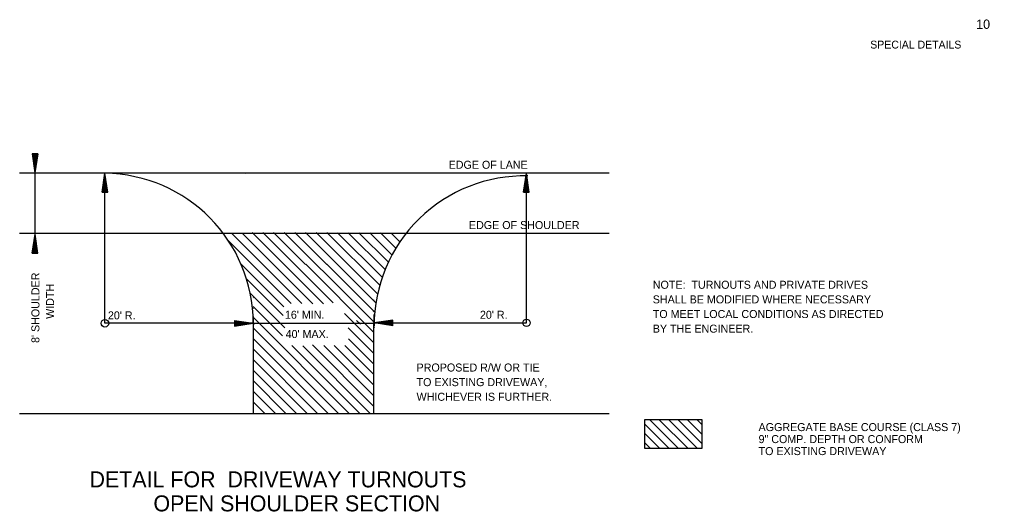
# Model space of a CAD drawing. Extents: x 635488 to 635865, y 290537 to 290973.
# Drawn here: x 635707.6 to 635780.4, y 290932.7 to 290969.7 of the extents above; entities that cross this region are included whole.
import ezdxf

# ---------------------------------------------------------------- set-up
doc = ezdxf.new("R2010")
doc.units = 0
for name, color, linetype in [('Default', 7, 'Continuous'), ('E_Existing ROW', 7, 'Continuous'), ('R_Alt Surface', 7, 'Continuous'), ('R_Alt Surface Annot', 7, 'Continuous')]:
    doc.layers.add(name, color=color, linetype=linetype)

msp = doc.modelspace()

# ---------------------------------------------------------------- linework, layer by layer
at = {"layer": 'Default'}
for p, q in [((635708.577, 290959.558), (635708.789, 290958.143)), ((635709.002, 290959.558), (635708.577, 290959.558)), ((635708.61, 290959.558), (635708.789, 290958.378)), ((635708.65, 290959.558), (635708.789, 290958.621)), ((635708.686, 290959.558), (635708.789, 290958.857)), ((635708.72, 290959.558), (635708.789, 290959.098)), ((635708.756, 290959.558), (635708.789, 290959.329)), ((635709.002, 290959.558), (635708.789, 290958.143)), ((635708.855, 290959.558), (635708.789, 290959.098)), ((635708.932, 290959.558), (635708.789, 290958.621)), ((635708.968, 290959.558), (635708.789, 290958.378)), ((635708.893, 290959.558), (635708.789, 290958.857)), ((635708.823, 290959.558), (635708.789, 290959.329)), ((635707.625, 290958.143), (635751.829, 290958.143)), ((635708.795, 290953.624), (635708.795, 290958.143)), ((635713.824, 290956.695), (635714.036, 290958.107)), ((635713.857, 290956.695), (635714.036, 290957.869)), ((635714.246, 290956.695), (635714.036, 290958.107)), ((635714.036, 290946.854), (635714.036, 290958.107)), ((635714.212, 290956.695), (635714.036, 290957.869)), ((635724.547, 290958.096), (635724.567, 290958.157)), ((635724.567, 290958.137), (635724.547, 290958.096)), ((635724.547, 290958.096), (635724.567, 290958.116)), ((635745.428, 290956.701), (635745.641, 290958.116)), ((635745.462, 290956.701), (635745.641, 290957.874)), ((635745.853, 290956.701), (635745.641, 290958.116)), ((635745.641, 290946.884), (635745.641, 290958.116)), ((635745.816, 290956.701), (635745.641, 290957.874)), ((635713.893, 290956.695), (635714.036, 290957.626)), ((635713.929, 290956.695), (635714.036, 290957.393)), ((635713.969, 290956.695), (635714.036, 290957.152)), ((635714.176, 290956.695), (635714.036, 290957.626)), ((635714.139, 290956.695), (635714.036, 290957.393)), ((635714.105, 290956.695), (635714.036, 290957.152)), ((635745.498, 290956.701), (635745.641, 290957.633)), ((635745.534, 290956.701), (635745.641, 290957.399)), ((635745.569, 290956.701), (635745.641, 290957.158)), ((635745.78, 290956.701), (635745.641, 290957.633)), ((635745.744, 290956.701), (635745.641, 290957.399)), ((635745.71, 290956.701), (635745.641, 290957.158)), ((635713.824, 290956.695), (635714.246, 290956.695)), ((635714.001, 290956.695), (635714.036, 290956.917)), ((635714.07, 290956.695), (635714.036, 290956.917)), ((635745.428, 290956.701), (635745.853, 290956.701)), ((635745.605, 290956.701), (635745.641, 290956.923)), ((635745.674, 290956.701), (635745.641, 290956.923)), ((635707.625, 290953.624), (635751.829, 290953.624)), ((635708.587, 290952.12), (635708.798, 290953.535)), ((635709.011, 290952.12), (635708.798, 290953.535)), ((635708.622, 290952.12), (635708.798, 290953.293)), ((635708.658, 290952.12), (635708.798, 290953.053)), ((635708.691, 290952.12), (635708.798, 290952.818)), ((635708.974, 290952.12), (635708.798, 290953.293)), ((635708.941, 290952.12), (635708.798, 290953.053)), ((635708.9, 290952.12), (635708.798, 290952.818)), ((635708.587, 290952.12), (635709.011, 290952.12)), ((635708.73, 290952.12), (635708.798, 290952.577)), ((635708.765, 290952.12), (635708.798, 290952.343)), ((635708.867, 290952.12), (635708.798, 290952.577)), ((635708.831, 290952.12), (635708.798, 290952.343)), ((635729.092, 290951.29), (635734.196, 290946.17)), ((635730.681, 290951.281), (635734.262, 290947.69)), ((635724.649, 290950.198), (635727.409, 290947.428)), ((635732.881, 290949.867), (635734.35, 290948.394)), ((635724.928, 290949.125), (635727.532, 290946.514)), ((635725.923, 290949.622), (635727.445, 290948.096)), ((635725.158, 290948.102), (635727.35, 290945.903)), ((635733.116, 290948.046), (635734.196, 290946.962)), ((635723.746, 290947.064), (635725.158, 290946.854)), ((635723.746, 290947.064), (635723.746, 290946.64)), ((635723.746, 290947.031), (635724.919, 290946.854)), ((635723.746, 290946.994), (635724.679, 290946.854)), ((635723.746, 290946.953), (635724.442, 290946.854)), ((635723.746, 290946.922), (635724.203, 290946.854)), ((635725.158, 290947.352), (635725.158, 290946.824)), ((635725.158, 290947.31), (635732.352, 290940.094)), ((635731.993, 290947.586), (635734.196, 290945.377)), ((635734.196, 290947.505), (635734.196, 290946.86)), ((635735.626, 290947.097), (635734.215, 290946.884)), ((635735.626, 290947.064), (635734.451, 290946.884)), ((635735.626, 290947.028), (635734.694, 290946.884)), ((635735.626, 290946.991), (635734.927, 290946.884)), ((635735.626, 290946.958), (635735.167, 290946.884)), ((635735.626, 290946.918), (635735.402, 290946.884)), ((635735.626, 290946.675), (635735.626, 290947.097)), ((635725.158, 290946.854), (635714.036, 290946.854)), ((635723.746, 290946.886), (635723.967, 290946.854)), ((635723.746, 290946.64), (635725.158, 290946.854)), ((635723.746, 290946.782), (635724.203, 290946.854)), ((635723.746, 290946.711), (635724.679, 290946.854)), ((635723.746, 290946.673), (635724.919, 290946.854)), ((635723.746, 290946.747), (635724.442, 290946.854)), ((635723.746, 290946.819), (635723.967, 290946.854)), ((635725.158, 290946.854), (635725.158, 290940.094)), ((635725.158, 290946.854), (635733.126, 290946.854)), ((635725.158, 290946.518), (635731.56, 290940.094)), ((635732.268, 290946.518), (635734.196, 290944.585)), ((635732.904, 290946.854), (635734.247, 290946.854)), ((635734.196, 290940.082), (635734.196, 290946.884)), ((635735.626, 290946.675), (635734.215, 290946.884)), ((635734.215, 290946.884), (635745.641, 290946.884)), ((635735.626, 290946.709), (635734.451, 290946.884)), ((635735.626, 290946.744), (635734.694, 290946.884)), ((635735.626, 290946.782), (635734.927, 290946.884)), ((635735.626, 290946.818), (635735.167, 290946.884)), ((635735.626, 290946.851), (635735.402, 290946.884)), ((635725.158, 290945.724), (635730.77, 290940.094)), ((635732.299, 290945.696), (635734.196, 290943.792)), ((635725.158, 290944.932), (635729.98, 290940.094)), ((635728.051, 290945.198), (635733.14, 290940.094)), ((635728.874, 290945.167), (635733.932, 290940.094)), ((635729.59, 290945.243), (635734.196, 290940.622)), ((635730.441, 290945.179), (635734.196, 290941.413)), ((635731.233, 290945.177), (635734.196, 290942.207)), ((635732.026, 290945.176), (635734.196, 290943)), ((635725.158, 290944.138), (635729.188, 290940.094)), ((635725.158, 290943.344), (635728.4, 290940.094)), ((635725.158, 290942.552), (635727.61, 290940.094)), ((635725.158, 290941.76), (635726.818, 290940.094)), ((635725.158, 290940.968), (635726.03, 290940.094)), ((635707.625, 290940.094), (635751.829, 290940.094))]:
    msp.add_line(p, q, dxfattribs=at)
for points in [[(635723.526, 290953.624), (635728.808, 290948.338)], [(635724.323, 290953.624), (635729.63, 290948.322)], [(635725.069, 290953.677), (635730.432, 290948.315)], [(635725.868, 290953.674), (635731.16, 290948.386)], [(635726.671, 290953.671), (635729.071, 290951.27)], [(635727.471, 290953.665), (635733.11, 290948.04)], [(635728.271, 290953.665), (635730.669, 290951.27)], [(635729.08, 290953.663), (635732.881, 290949.867)], [(635729.877, 290953.66), (635732.274, 290951.27)], [(635730.678, 290953.657), (635734.636, 290949.702)], [(635731.481, 290953.651), (635734.827, 290950.308)], [(635732.28, 290953.651), (635735.047, 290950.895)], [(635733.083, 290953.651), (635735.289, 290951.449)], [(635733.886, 290953.648), (635735.557, 290951.977)], [(635734.688, 290953.648), (635735.848, 290952.487)], [(635735.504, 290953.624), (635736.158, 290952.97)], [(635723.286, 290953.065), (635728.004, 290948.343)], [(635724.233, 290951.319), (635725.923, 290949.622)], [(635732.272, 290951.27), (635734.475, 290949.059)], [(635725.158, 290948.797), (635725.18, 290948.774)], [(635734.135, 290948.609), (635734.196, 290948.547)], [(635725.158, 290947.998), (635725.174, 290947.974)], [(635734.137, 290947.8), (635734.229, 290947.71)], [(635725.152, 290947.204), (635725.171, 290947.182)], [(635732.904, 290947.075), (635733.194, 290946.78)], [(635734.139, 290947), (635734.196, 290946.946)], [(635725.171, 290946.816), (635725.228, 290946.758)], [(635734.175, 290946.598), (635734.242, 290946.534)]]:
    msp.add_lwpolyline(points, dxfattribs=at)
for centre in [(635714.036, 290946.854), (635745.64, 290946.885)]:
    msp.add_circle(centre, 0.282, dxfattribs=at)
for centre, radius, start, end in [((635713.893, 290946.839), 11.268, 0.07639, 89.27429), ((635745.485, 290946.64), 11.273, 88.75379, 180)]:
    msp.add_arc(centre, radius, start, end, dxfattribs=at)
at = {"layer": 'E_Existing ROW'}
for p, q in [((635757.05, 290937.452), (635754.868, 290939.635)), ((635757.757, 290937.452), (635755.575, 290939.635)), ((635758.464, 290937.452), (635756.282, 290939.635)), ((635758.789, 290937.835), (635756.989, 290939.635)), ((635758.789, 290938.542), (635757.696, 290939.635)), ((635758.789, 290939.249), (635758.403, 290939.635)), ((635756.343, 290937.452), (635754.508, 290939.287)), ((635755.636, 290937.452), (635754.508, 290938.58)), ((635754.928, 290937.452), (635754.508, 290937.873))]:
    msp.add_line(p, q, dxfattribs=at)
msp.add_lwpolyline([(635754.508, 290939.635), (635758.789, 290939.635), (635758.789, 290937.452), (635754.508, 290937.452)], close=True, dxfattribs=at)

# ---------------------------------------------------------------- texts
at = {"layer": 'Default'}
for s, height, p in [('EDGE OF LANE', 0.6, (635739.805, 290958.447)), ('EDGE OF SHOULDER', 0.6, (635741.327, 290953.923)), ('NOTE:  TURNOUTS AND PRIVATE DRIVES', 0.6, (635755.111, 290949.444)), ('SHALL BE MODIFIED WHERE NECESSARY', 0.6, (635755.111, 290948.346)), ("20' R.", 0.6, (635714.261, 290947.148)), ("16' MIN.", 0.6, (635727.53, 290947.195)), ("20' R.", 0.6, (635742.153, 290947.194)), ('TO MEET LOCAL CONDITIONS AS DIRECTED', 0.6, (635755.111, 290947.249)), ("40' MAX.", 0.6, (635727.584, 290945.747)), ('BY THE ENGINEER.', 0.6, (635755.111, 290946.151)), ('PROPOSED R/W OR TIE', 0.6, (635737.401, 290943.236)), ('TO EXISTING DRIVEWAY,', 0.6, (635737.401, 290942.138)), ('WHICHEVER IS FURTHER.', 0.6, (635737.401, 290941.041)), ('DETAIL FOR  DRIVEWAY TURNOUTS', 1.2, (635712.881, 290934.544)), ('OPEN SHOULDER SECTION', 1.2, (635717.673, 290932.742))]:
    msp.add_text(s, height=height, dxfattribs=at).set_placement(p)
for s, p in [("8' SHOULDER", (635709.125, 290945.378)), ('WIDTH', (635710.222, 290947.185))]:
    msp.add_text(s, height=0.6, rotation=90, dxfattribs=at).set_placement(p)
at = {"layer": 'E_Existing ROW'}
for s, p in [('AGGREGATE BASE COURSE (CLASS 7)', (635763.041, 290938.765)), ('9" COMP. DEPTH OR CONFORM', (635763.041, 290937.865)), ('TO EXISTING DRIVEWAY', (635763.041, 290936.965))]:
    msp.add_text(s, height=0.6, dxfattribs=at).set_placement(p)
at = {"layer": 'R_Alt Surface'}
msp.add_text('10', height=0.7, dxfattribs=at).set_placement((635779.357, 290968.943))
at = {"layer": 'R_Alt Surface Annot'}
msp.add_text('SPECIAL DETAILS', height=0.58876, dxfattribs=at).set_placement((635771.416, 290967.468))

doc.saveas('drawing.dxf')
